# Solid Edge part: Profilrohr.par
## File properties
Username: bmolnar
Dokumentum tartalom típus: 0
Author: bmolnar
Last saved by: bmolnar
Revision: 77
Sűrűség: 0,000 kg/m^3
Pontosság: 0,990
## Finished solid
Body 1: solid body, 115 faces, 338 edges, 224 vertices.
  Faces by surface: cylinder 59, plane 56
  Edges by curve: line 220, circle 118
Bounding box of the edges (mm): 77.000 x 77.000 x 31.500, from (-38.5, -38.5, 0) to (38.5, 38.5, 31.5).
Cylindrical faces by radius (mm): R0.15 x24, R0.25 x24, R1 x4, R12 x4, R13.5 x2, R31.5 x1
Planar faces by outward normal: +x 13, +y 14, +z 1, -x 13, -y 14, -z 1
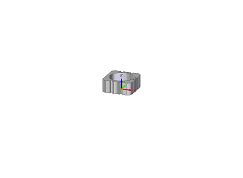
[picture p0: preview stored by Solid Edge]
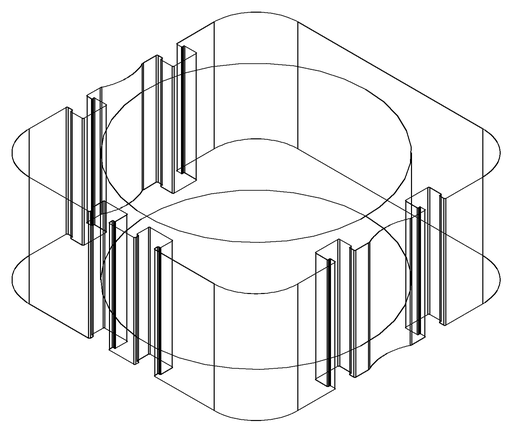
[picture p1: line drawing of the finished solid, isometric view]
